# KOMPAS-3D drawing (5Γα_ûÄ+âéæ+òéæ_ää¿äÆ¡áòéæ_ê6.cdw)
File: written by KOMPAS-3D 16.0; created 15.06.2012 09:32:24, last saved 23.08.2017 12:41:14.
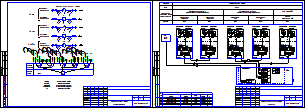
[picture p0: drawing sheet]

Sheets 1-2: A3, landscape

Title block, sheet 1: name: Руководство по эксплуатации; sheet number: 1; sheets: 27; organisation: ООО"Интелприбор"; sheet format: A3; stored path: W:\Users\smirnov_v\Desktop\шаблоны\4-х трубка\4-х трубка ГВС-max.cdw / D:\Проекты\Лыткарино\ул. Квартал 3А, д.25\710.74 РП.cdw; file name: 4-х трубка ГВС-max.cdw / 710.74 РП.cdw; cell 51: МО, Воскресенсикй р-н, п. Хорлово, ул. Интернациональная, д. 4; cell 320: Р
Title block, sheet 2: sheet number: 2

Views: Вид 2, Вид 3
Referenced files in C:\Program Files (x86)\ASCON\KOMPAS-3D V16\Sys\: spds.lcs, EngSys.lcs, GRAPHIC.LHS
Referenced files: graphic.tdp
Referenced files in W:\Users\smirnov_v\Desktop\шаблоны\4-х трубка\: 4-х трубка ГВС-max.cdw
Referenced files in D:\Проекты\Лыткарино\ул. Квартал 3А, д.25\: 710.74 РП.cdw
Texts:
  Смирнов В.С.
  УУ-3423
  GOST Common
  Normal
  List Paragraph
  heading 3
  для схемы
  txt
  Т0-элементы
  Преобразователь расхода
  Термопреобразователь
  Преобразователь давления
  Преобразователь цифровой
  Системный блок МКТС
  приборы
  по месту
  шкаф
  учета
  UQIES
  Подающий
  трубопровод
  Обратный
  УУГВС
  УУТЭ
  Вводной
  УУХВС
  Функциональная схема
  Плата подключений
  Агрегат
  Системный блок  МКТС
  Среда
  Вода
  параметра и место
  отбора импульса
  Учет тепловой энергии и
  теплоносителя системы отопления
  отопления
  расхода горячей водысистемы ГВС
  трубопровод ХВС
  Узел учета ХВС
  ГВС
  ИМ1
  ИМ2
  ИМ3
  ИМ4
  ИМ5
  СБ МКТС
  ВРУ
  UP+
  UP-
  ИМП
  Лин
  Измерительный
  модуль М121
  Pt 100
  Преобразователь
  температуры
  давления
  каб.
  Начало
  трассы
  Трассы
  Марка
  Проложен
  Изм. модуль (Т1)
  Изм. модуль (Т2)
  Изм. модуль (Т3)
  Изм. модуль (Т4)
  Изм. модуль (В1)
  ВРУ 220В, 50 Гц
  ИМ (Т1)
  ИМ (Т3)
  FTP
  ПВС
  Конец
  Кол-во и
  сеч. жил
  Длина,
  Размеры, параметризация
  сит. план
  подача ГВС
  обратка ГВС
  хвс
  обратка
  POLYLINE_STYLE_0.25_RGB_0_0_0
  стены
  Основная (не является границей для штриховки)
  POLYLINE_STYLE_0.18_RGB_0_0_0
  ХВС
  зеленая
  Красная тонкая
  арматура
  Подача
  Скрытая линия
  Ось Z
  Ось Y
  Ось X
  Образующая трубопровода (проектируемого)
  Трубопровод толщиной 0.6мм (одна линия)
  Трубопровод толщиной 1.2мм (одна линия)
  Трубопровод толщиной 1.0мм (одна линия)
  Трубопровод толщиной 0.8мм (одна линия)
  Трубопровод существующий (одна линия)
  Трубопровод невидимый (одна линия)
  Трубопровод демонтируемый (одна линия)
  Осевая трубопровода
  Осевая трубопровода (демонтируемого)
  Образующая трубопровода (существующего)
  Образующая трубопровода (невидимого)
  Изолированный трубопровод проектируемый (одна линия)
  Изолированный трубопровод существующий (одна линия)
  Образующая изоляции
  Изоляция
  Изолированный трубопровод невидимый (одна линия)
  Штрих пвс 075
  штрих пвс 2,5
  существующее оборудование
  Существующее оборудование
  K5LT_BASIC_RGB_0_0_255_THICK_0.53
  POLYLINE_STYLE_1.51_RGB_0_0_255
  POLYLINE_STYLE_0.50_RGB_128_128_128
  K5LT_AXLED_RGB_255_128_0_SC_1_THICK_0.18
  ACAD_ISO04W100_RGB_0_0_0_SC_1_THICK_0.18
  тонкая черная
  тонкая красная
  тонкая синяя
  тонкая оранж
  красн штрих
  пломбировка
  Провода
  синий штрих
  Стили документа
  G2co
  расход вторичной воды объемный
  расход вторичной воды объемный при 70гр
  Gco
  расход теплоносителя массовый
  расход теплоносит объемн подающ
  расход теплоносит объемн обр
  Лапир
  Ghvs
  Im1
  Im2
  Im3
  Im4
  Im5
  Khvs
  норматив ХВС
  число подъездов
  число этажей
  Nkv
  число квартир
  тепловая нагрузка на отопление
  сумма Q
  Qgvs
  тепловая нагрузка ГВС
  тепловая нагрузка на циркуляцию ГВС
  иммитовставка или под манометр
  ro1
  ro2
  ro3
  ro4
  верх предел темп граф
  нижн предел темп граф
  темп подачи ГВС
  темп обр ГВС
  темр хол воды
  vzdh
  Kchn
  Ktp
  Knp
  tnv
  Vклап
  KLP
  RPD
  RDS
  PUMP
  ro5
  beta
  tnv98
  Shifr
  Переход ГОСТ 17378-2001
  Переход
  ГОСТ
  Сталь 09Г2С ГОСТ 19281-89
  Втулка 20x50
  Лит-Масса-Масштаб
  Материал-Предприятие
  Title Specification
  Body Specification ( left align )
  Body Specificaton ( centered )
  Поз.
  Кол.
  Приме-
  чание
  Таблица спецификации
  Засыпка
  Штрих3
  Штрих2
  Штрих1
  Песок
  Штр0.5пр7
  Штр0.5пр12
  Штр0.3пр10
  Штр1.4пр21.21
  Штр1пр15
  Штр2.12пр35
  Штр1.5пр25
  Штр2.82пр42.42
  Штр2пр30
  SACNCR_ISO 1
  Электрощитовая
  Пр-1
  Ок-1
  Обозначение стандарта
  Типоразмер
  Пояснительная записка
  автоматизации
  Рабочие чертежи основного комплекта. ГОСТ Р 21.1101-2009 Ф3
  Стадия
  Лист
  Листов
  Изм.
  Кол.уч.
  №док.
  Подп.
  Дата
  Разраб.
  Пров.
  Т.контр.
  Н.контр.
  Утв.
  Изменение
  Номер документа
  Подпись
  Наименование объекта строительства, в состав которого входит здание, наим. микр
  Наименование здания (сооружения)
  Порядковый номер листа
  Количество листов в документе
  Наименование изображения
  Индекс предприятия, выпускающего документ
  Инв. № подл.
  Подп. и дата
  Взам. инв. №
  Инвентарный номер подлинника
  Подпись принявшего подлинник на хранение
  Инвентарный номер подлинника, взамен которого выпущен данный подлинник
  Согласовано
  Формат листа
  Согласование
  03 Рабочие чертежи основного комплекта. ГОСТ Р 21.1101-2009 Ф3
  Схема соединений внешних
  проводок
Dimensions and other numbers on the sheet: 21; 2; 4; 1,2,3,4,5; 6,7,8,9,10; 11,12,13,14,15; 16,17,18,19,20; 6; 5; 1; 3; 12; 16; 17; 11; 7; 18; 0; 5,0; 3,2388; 0,0400; 40; 95; 3,1876; 4,5; 0,0; 0,0000; 70; 9; 10; 13; 14; 8; 19; 15; 20; 220В; 50Гц; 4-20; 2x2x0,52; 3х0,75; 09Г2С; 27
